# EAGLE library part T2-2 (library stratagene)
Netztrafo
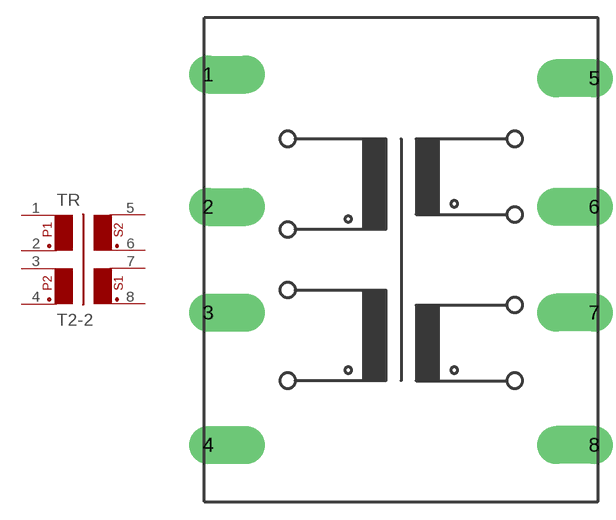
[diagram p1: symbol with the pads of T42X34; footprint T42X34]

Designator prefix TR

## T2-2  [T42X34]
1  1  pas
2  2  pas
3  3  pas
4  4  pas
5  8  pas
6  7  pas
7  6  pas
8  5  pas

## Footprint T42X34 (pad centres in mm)
Mexiko-Trafo 42×34 mm, seltsame Pinpositionierung
drill 1.5 pad 3.175 offset: 1 -16.192,15.557; 2 -16.192,4.445; 3 -16.192,-4.445; 4 -16.192,-15.557; 5 16.192,15.24; 6 16.192,4.445; 7 16.192,-4.445; 8 16.192,-15.557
